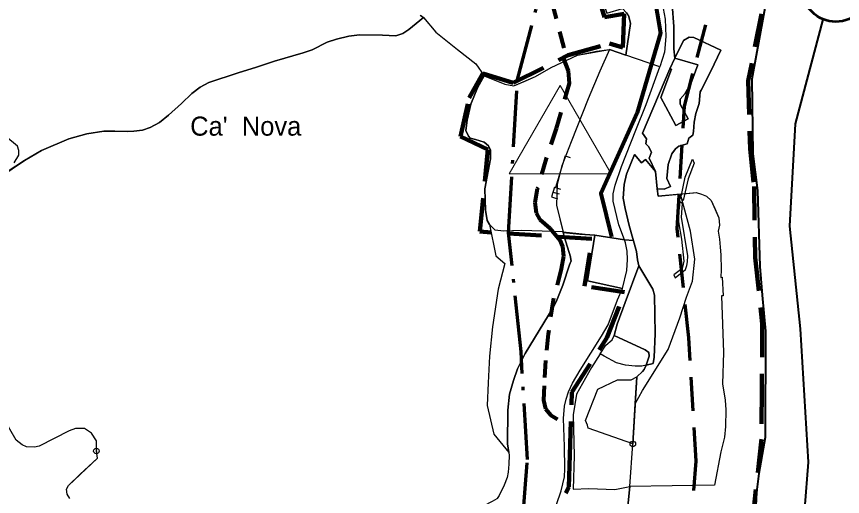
# Model space of a CAD drawing. Extents: x 645880 to 658994, y 884400 to 894744.
# Drawn here: x 657672 to 658409, y 893255 to 893684 of the extents above; entities that cross this region are included whole.
import ezdxf
from ezdxf.enums import TextEntityAlignment as Align

# ---------------------------------------------------------------- set-up
doc = ezdxf.new("R2010")
doc.units = 0
doc.header["$LTSCALE"] = 10
doc.header["$PDMODE"] = 32
doc.header["$PDSIZE"] = 5
for name, pattern in [('DOT_DASHED', [7.7, 5, -1.2, 0.3, -1.2]), ('MEDIUM_DASHED', [4.5, 3, -1.5]), ('SHORT_DASHED', [2.7, 1.5, -1.2])]:
    doc.linetypes.add(name, pattern=pattern)
for name, color, linetype, lineweight in [('1', 7, 'Continuous', 25), ('11', 7, 'Continuous', 25), ('13', 7, 'Continuous', 25), ('15', 7, 'MEDIUM_DASHED', 100), ('16', 7, 'Continuous', 25), ('17', 7, 'Continuous', 25), ('23', 7, 'Continuous', 25), ('29', 7, 'Continuous', 25), ('31', 7, 'Continuous', 25), ('40', 7, 'Continuous', 80), ('41', 7, 'Continuous', 40), ('43', 7, 'Continuous', 25), ('45', 7, 'Continuous', 25), ('55', 7, 'Continuous', 25), ('58', 7, 'Continuous', 25), ('59', 7, 'Continuous', 40), ('6', 7, 'Continuous', 25), ('8', 7, 'Continuous', 25)]:
    doc.layers.add(name, color=color, linetype=linetype, lineweight=lineweight)
doc.layers.add('60', color=7, linetype='Continuous')

msp = doc.modelspace()

# ---------------------------------------------------------------- linework, layer by layer
at = {"layer": '1'}
msp.add_lwpolyline([(658254.57, 893636.97), (658256.11, 893636.78), (658246.68, 893611.35), (658259.96, 893586.31), (658270.93, 893592.48), (658263.81, 893605.38), (658263.81, 893610), (658268.43, 893614.82), (658273.24, 893623.49), (658279.59, 893640.44), (658259, 893646.54)], close=True, dxfattribs=at)
for points in [[(658221.65, 893302.26), (658181.77, 893316.46), (658181.34, 893319.06), (658179.34, 893323.06), (658190.47, 893351.06), (658208.09, 893359.56)], [(658208.09, 893359.56), (658220.22, 893359.56), (658225.09, 893362.17), (658221.65, 893302.26)]]:
    msp.add_lwpolyline(points, dxfattribs=at)
msp.add_point((658221.65, 893302.26), dxfattribs=at)
at = {"layer": '11'}
msp.add_lwpolyline([(658203.33, 893395.05), (658205.08, 893398.92), (658232.75, 893386.21), (658235.81, 893383.96), (658236.17, 893380.56), (658234.55, 893375.56), (658233.57, 893372.65), (658229.56, 893371.79), (658223.86, 893371.79), (658214.98, 893372.47), (658207.14, 893374.72), (658196.05, 893380.49), (658192.6, 893382.61), (658197.59, 893390.43)], close=True, dxfattribs=at)
at = {"layer": '13'}
for points in [[(658192.6, 893382.61), (658184.84, 893370.51), (658171.43, 893346.66), (658168.44, 893328.22), (658169.34, 893291.72), (658168.29, 893261.9), (658182.5, 893262.45), (658205.56, 893261.71), (658218.93, 893264.19), (658221.65, 893302.26), (658181.77, 893316.46), (658181.34, 893319.06), (658179.34, 893323.06), (658190.47, 893351.06), (658208.09, 893359.56), (658220.22, 893359.56), (658225.09, 893362.17), (658230.3, 893366.95), (658231.67, 893368.82), (658232.92, 893371.32)], [(658232.92, 893371.32), (658233.57, 893372.65), (658229.56, 893371.79), (658223.86, 893371.79), (658214.98, 893372.47), (658207.14, 893374.72), (658196.05, 893380.49), (658192.6, 893382.61)]]:
    msp.add_lwpolyline(points, dxfattribs=at)
at = {"layer": '15'}
for points in [[(658271.86, 893859.9), (658294.4, 893888.67), (658333.87, 893869.22), (658397.09, 893835.57), (658355.34, 893760.97), (658345.21, 893730.15), (658324.56, 893626.35), (658326.18, 893565.54), (658329.82, 893531.88), (658330.62, 893468.63), (658337.11, 893409.83), (658336.7, 893350.23), (658336.29, 893306.44), (658326.56, 893216.03)], [(658141.8, 893218.08), (658164.49, 893263.9), (658165.31, 893292.28), (658167.33, 893348.61), (658198.53, 893396.86), (658214.34, 893437.82), (658178.68, 893443.09), (658185.17, 893485.26), (658085.26, 893491.71), (658092.37, 893565.14), (658068.06, 893576.49), (658075.76, 893610.95), (658087.91, 893632.85), (658115.06, 893624.33), (658164.09, 893649.07), (658200.96, 893659.61), (658212.72, 893655.96), (658213.93, 893685.96), (658196.51, 893683.12), (658187.58, 893713.13)]]:
    msp.add_lwpolyline(points, dxfattribs=at)
at = {"layer": '16'}
msp.add_lwpolyline([(657669.76, 893553.16), (657674.01, 893559.93), (657674.11, 893563.98), (657672.88, 893568.11), (657662.51, 893576.7)], dxfattribs=at)
at = {"layer": '17'}
for points in [[(658032.01, 893684.94), (658034.95, 893682.87), (658021.82, 893672.16), (658016.4, 893668.46), (658010.12, 893666.52), (657998.4, 893666.94), (657977.8, 893667.16), (657968.26, 893666.08), (657957.2, 893663.48), (657948.96, 893660.66), (657935.52, 893653.92), (657927.5, 893651.1), (657901.92, 893643.72), (657885.86, 893638.52), (657869.6, 893633.32), (657843.58, 893624.86), (657835.78, 893620.74), (657828.4, 893615.08), (657819.08, 893606.18), (657807.36, 893595.56), (657799.56, 893589.04), (657791.1, 893584.7), (657784.16, 893582.32), (657776.58, 893581.24), (657770.72, 893581.02), (657759.66, 893581.46), (657749.9, 893581.46), (657734.72, 893579.06), (657718.72, 893574.38), (657694.26, 893564.16), (657678.94, 893555.26), (657664.52, 893545.6)], [(657807.36, 893595.56), (657819.08, 893606.18), (657828.4, 893615.08), (657835.78, 893620.74), (657843.58, 893624.86), (657869.6, 893633.32), (657885.86, 893638.52), (657901.92, 893643.72), (657927.5, 893651.1), (657935.52, 893653.92), (657948.96, 893660.66), (657957.2, 893663.48), (657968.26, 893666.08), (657977.8, 893667.16), (657998.4, 893666.94), (658010.12, 893666.52), (658016.4, 893668.46), (658021.82, 893672.16), (658021.82, 893672.16), (658034.95, 893682.87), (658045.9, 893669.76), (658065.2, 893654.14), (658081.68, 893641.56), (658089.12, 893630.86), (658082.98, 893620.06), (658077.06, 893605.48), (658073.9, 893591.18), (658072.62, 893582.08), (658074.94, 893576.8), (658076.42, 893575.1), (658078.86, 893574.58), (658081.3, 893574.04), (658085.1, 893572.78), (658088.9, 893571.5), (658092.92, 893568.34), (658094.82, 893564.52), (658094.6, 893556.7), (658089.74, 893529.92), (658090.38, 893510.88), (658091.64, 893501.78), (658093.76, 893498.18)], [(657656.7, 893540.36), (657678.94, 893555.26), (657694.26, 893564.16), (657718.72, 893574.38), (657734.72, 893579.06), (657749.9, 893581.46), (657759.66, 893581.46), (657770.72, 893581.02), (657776.58, 893581.24), (657784.16, 893582.32), (657791.1, 893584.7), (657799.56, 893589.04), (657807.36, 893595.56)], [(657669.76, 893553.16), (657674.01, 893559.93), (657674.11, 893563.98), (657672.88, 893568.11), (657662.51, 893576.7)], [(658093.76, 893498.18), (658099.47, 893470.09), (658107.46, 893463.38), (658101.42, 893440.46), (658096.54, 893406.63), (658093.83, 893380.57)], [(658187.72, 893488.65), (658174.36, 893489.35), (658159.58, 893490.91)], [(658159.58, 893490.91), (658160.45, 893487.38), (658166.18, 893469.21)], [(658212.49, 893441.12), (658181.08, 893447.74), (658187.72, 893488.64)], [(658166.18, 893469.21), (658166.47, 893466.66), (658166.56, 893465.61), (658165.26, 893462.03), (658159.28, 893443.84), (658153.39, 893429.02)], [(658085.38, 893195.06), (658094.98, 893197.2), (658106.44, 893201.12), (658121.82, 893208.1), (658134.52, 893216.7), (658142.56, 893225.66), (658145.96, 893231.74), (658153.66, 893248.38), (658157.6, 893260.38), (658160.82, 893273.08), (658161, 893280.06), (658160.64, 893299.92), (658159.92, 893324.98), (658160.64, 893335.9), (658162.24, 893342.34), (658164.22, 893348.78), (658167.8, 893356.48), (658174.76, 893368.12), (658193.74, 893398.56), (658199.64, 893408.58), (658207.86, 893430.96), (658212.5, 893441.11)], [(658153.39, 893429.02), (658150.62, 893424.01), (658138.04, 893403.48)], [(658138.04, 893403.48), (658125.48, 893382.95), (658118.84, 893369.31), (658115.14, 893358.95)], [(658093.83, 893380.57), (658092.56, 893356.78), (658091.6, 893336.67), (658097.69, 893311.05), (658110.91, 893294.77)], [(658115.14, 893358.95), (658111.52, 893346.72), (658110.18, 893332.4)], [(657732.7, 893315.98), (657729.16, 893316.2), (657724.48, 893316.2), (657718.92, 893313.98), (657692.26, 893300.2), (657688.04, 893299.52), (657680.92, 893299.74), (657676.92, 893301.52), (657671.6, 893305.52), (657655.6, 893333.1)], [(658110.18, 893332.4), (658109.88, 893302.5), (658110.91, 893294.77)], [(657719.58, 893253.72), (657717.14, 893257.5), (657716.48, 893261.94), (657718.26, 893265.06), (657728.48, 893275.06), (657744.04, 893289.52), (657743.16, 893295.98), (657743.38, 893305.08), (657738.94, 893311.76), (657732.7, 893315.98), (657729.16, 893316.2), (657724.48, 893316.2), (657718.92, 893313.98), (657692.26, 893300.2), (657688.04, 893299.52), (657680.92, 893299.74), (657676.92, 893301.52), (657671.6, 893305.52)], [(657719.58, 893253.72), (657717.14, 893257.5), (657716.48, 893261.94), (657718.26, 893265.06), (657744.04, 893289.52), (657743.16, 893295.98), (657743.38, 893305.08), (657738.94, 893311.76), (657732.7, 893315.98)], [(658110.91, 893294.77), (658111.25, 893292.29), (658111.1, 893284.1), (658110.58, 893277.1), (658109.49, 893272.37), (658106.8, 893265.52), (658102.48, 893256.3), (658100.61, 893253.67), (658100.3, 893253.42), (658096.11, 893250.82), (658088.67, 893247.03), (658082.93, 893245.51), (658068.56, 893241.98), (658059.08, 893238.95)], [(658110.91, 893294.77), (658111.25, 893292.29), (658111.1, 893284.1), (658110.58, 893277.1), (658109.49, 893272.37), (658106.8, 893265.52), (658102.48, 893256.3), (658100.61, 893253.67), (658100.3, 893253.42), (658096.11, 893250.82), (658088.67, 893247.03), (658082.93, 893245.51), (658068.56, 893241.98), (658059.08, 893238.95), (658062.89, 893238.62), (658071.37, 893236.58)]]:
    msp.add_lwpolyline(points, dxfattribs=at)
msp.add_point((657743.16, 893295.98), dxfattribs=at)
at = {"layer": '23'}
msp.add_lwpolyline([(658239.84, 893374.06), (658240.73, 893379.64), (658241.57, 893400.63), (658241.01, 893434.89), (658241.01, 893434.89), (658239.34, 893440.45), (658239.34, 893440.45), (658226.86, 893461.24), (658225.87, 893466.59), (658224.9, 893473.91), (658218.37, 893497.27), (658214.77, 893512.21), (658212.96, 893521.52), (658213.93, 893533.89), (658216.02, 893542.87), (658223.24, 893560.66), (658229.5, 893553.15), (658232.97, 893555.93), (658242, 893545.51), (658243.49, 893529.98), (658244.34, 893523.48), (658275.65, 893526.23), (658278.09, 893526.48), (658282.92, 893525.16), (658287.22, 893523.48), (658291.47, 893519.48), (658294.72, 893512.48), (658298.34, 893503.98), (658298.97, 893497.48), (658297.84, 893491.98), (658298.84, 893484.98), (658299.53, 893477.98), (658300.22, 893470.98), (658300.34, 893457.98), (658300.09, 893450.92), (658301.34, 893450.98), (658302.22, 893434.48), (658300.83, 893434.36), (658301.71, 893409.17), (658302.59, 893383.98), (658301.59, 893355.98), (658304.02, 893341.45), (658304.57, 893332.63), (658304.43, 893317.75), (658303.32, 893308.44), (658302.36, 893303.57), (658300.11, 893295.25), (658294.5, 893265.58), (658218.93, 893264.19), (658221.65, 893302.26), (658225.09, 893362.17), (658230.3, 893366.95), (658231.67, 893368.82), (658233.57, 893372.65)], close=True, dxfattribs=at)
for points in [[(658233.57, 893372.65), (658239.84, 893374.06), (658240.73, 893379.64), (658241.57, 893400.63), (658241.01, 893434.89), (658239.34, 893440.45), (658226.86, 893461.24), (658214.69, 893428.53), (658207.82, 893409.29)], [(658207.82, 893409.29), (658205.08, 893398.92), (658232.75, 893386.21), (658235.81, 893383.96), (658236.17, 893380.56), (658233.57, 893372.65)]]:
    msp.add_lwpolyline(points, dxfattribs=at)
at = {"layer": '29'}
for points in [[(658159.41, 893491.6), (658159.08, 893491.64), (658122.25, 893492.7), (658106.23, 893492.27), (658098.83, 893493.12), (658093.76, 893498.19), (658091.64, 893501.79), (658090.38, 893510.88), (658089.74, 893529.92), (658094.6, 893556.71), (658094.81, 893564.53), (658092.91, 893568.34), (658088.9, 893571.51), (658081.29, 893574.05), (658076.42, 893575.11), (658074.94, 893576.8), (658072.62, 893582.08), (658073.89, 893591.18), (658077.06, 893605.48), (658082.98, 893620.07), (658089.11, 893630.86), (658107.5, 893623.24), (658115.53, 893621.76), (658124.62, 893625.57), (658134.76, 893630.01), (658148.93, 893638.26), (658162.88, 893644.6), (658172.39, 893649.26), (658189.3, 893652.64), (658200.71, 893654.12)], [(658200.71, 893654.12), (658192.12, 893634.81), (658181.89, 893610.19), (658166.71, 893571.87), (658158.35, 893550.54), (658154.22, 893534.01)], [(658200.71, 893654.12), (658192.12, 893634.81), (658181.89, 893610.19), (658166.71, 893571.87), (658158.35, 893550.54), (658154.22, 893534.01)], [(658214.15, 893484.45), (658209.15, 893497.74), (658204.07, 893518.89), (658204.07, 893525.44), (658205.98, 893533.27), (658211.46, 893549.92), (658224.35, 893582.22), (658233.44, 893605.27), (658245.7, 893638.69), (658215.38, 893649.09), (658200.71, 893654.12)], [(658154.22, 893534.01), (658153.55, 893515.32), (658159.41, 893491.6), (658187.72, 893488.65), (658214.15, 893484.45)], [(658154.22, 893534.01), (658153.55, 893515.32), (658159.41, 893491.6)]]:
    msp.add_lwpolyline(points, dxfattribs=at)
at = {"layer": '31'}
for points in [[(658032.89, 893684.43), (658034.95, 893682.87), (658045.9, 893669.76), (658065.2, 893654.14), (658081.68, 893641.56)], [(658081.68, 893641.56), (658089.11, 893630.86), (658107.5, 893623.24), (658115.53, 893621.76), (658134.76, 893630.01), (658148.93, 893638.26), (658172.39, 893649.26), (658200.71, 893654.12), (658215.38, 893649.09), (658219.44, 893677.54), (658217.97, 893683.8)]]:
    msp.add_lwpolyline(points, dxfattribs=at)
at = {"layer": '40'}
msp.add_lwpolyline([(658295.38, 893902.63), (658239.03, 893844.15), (658220.24, 893804.47), (658234.85, 893737.64), (658246.33, 893668.72), (658225.46, 893597.71), (658193.11, 893525.66), (658202.5, 893487.02)], dxfattribs=at)
at = {"layer": '40', "lineweight": 13}
msp.add_lwpolyline([(658156.91, 893621.98), (658202.39, 893543.22), (658111.45, 893543.22)], close=True, dxfattribs=at)
at = {"layer": '41', "linetype": 'SHORT_DASHED', "lineweight": 80}
for points in [[(658135.58, 893749.15), (658142.74, 893722.59), (658163.03, 893644.67)], [(658159.84, 893645.97), (658164.05, 893635.3), (658164.78, 893624.03), (658153.15, 893583.65), (658144.42, 893557.09), (658136.42, 893529.8), (658134.24, 893517.8), (658135.33, 893508.34), (658138.6, 893502.52), (658147.69, 893494.88), (658156.42, 893483.97), (658158.97, 893478.51), (658159.69, 893469.77), (658157.87, 893458.5), (658150.5, 893430.49), (658146.17, 893400.48), (658143.7, 893376.65), (658142.49, 893354.25), (658141.88, 893341.36), (658143.7, 893333.72), (658148.42, 893327.9), (658154.6, 893324.26)]]:
    msp.add_lwpolyline(points, dxfattribs=at)
at = {"layer": '41', "lineweight": 25}
for points in [[(658106.23, 893492.27), (658098.84, 893493.12), (658093.76, 893498.18)], [(658093.76, 893498.18), (658099.47, 893470.09), (658107.46, 893463.38), (658101.42, 893440.46), (658096.54, 893406.63), (658093.83, 893380.57)], [(658159.41, 893491.6), (658159.08, 893491.64), (658122.26, 893492.7), (658106.24, 893492.26)], [(658110.91, 893294.77), (658109.88, 893302.5), (658110.18, 893332.4), (658111.52, 893346.72), (658115.14, 893358.95), (658118.84, 893369.31), (658125.48, 893382.95), (658138.04, 893403.48), (658150.62, 893424.01), (658153.39, 893429.02), (658159.28, 893443.84), (658165.26, 893462.03), (658166.56, 893465.61), (658166.47, 893466.66), (658166.18, 893469.21), (658160.45, 893487.38), (658159.58, 893490.91), (658159.41, 893491.6)], [(658093.83, 893380.57), (658092.56, 893356.78), (658091.6, 893336.67), (658097.69, 893311.05), (658110.91, 893294.77)]]:
    msp.add_lwpolyline(points, dxfattribs=at)
at = {"layer": '43'}
for points in [[(658331.19, 893240.81), (658332.04, 893259.38), (658334.17, 893275.89), (658339.7, 893308.07), (658339.7, 893308.07), (658339.95, 893402.88), (658337.12, 893435.1), (658335, 893460.46), (658332.88, 893528.33), (658328.64, 893561.23), (658327.93, 893627.72), (658344.82, 893720.42), (658354, 893748.52), (658365.31, 893773.2), (658399.94, 893835.58), (658339.26, 893842.99), (658337.08, 893841.74), (658335.74, 893840.98)], [(658256.72, 893694.42), (658258.32, 893674.7), (658258.32, 893654.72), (658259, 893646.54), (658266.93, 893662.14), (658272.03, 893665.22), (658275.95, 893665), (658300.19, 893653.48), (658291.22, 893634.81), (658282.46, 893617.87), (658281.84, 893616.48), (658280.84, 893605.98), (658277.97, 893596.98), (658276.34, 893589.48), (658276.06, 893585.23), (658275.78, 893580.98), (658275.28, 893577.73), (658271.59, 893574.98), (658270.22, 893569.98), (658262.59, 893567.98), (658259.72, 893565.48), (658256.47, 893560.98), (658253.22, 893551.48), (658251.97, 893538.98), (658255.22, 893531.98), (658249.47, 893529.48), (658243.49, 893529.98), (658244.34, 893523.48), (658278.09, 893526.48), (658282.92, 893525.16), (658287.22, 893523.48), (658291.47, 893519.48), (658298.34, 893503.98), (658298.97, 893497.48), (658297.84, 893491.98), (658298.84, 893484.98), (658299.53, 893477.98), (658300.22, 893470.98), (658300.34, 893457.98), (658300.09, 893450.92), (658301.34, 893450.98), (658302.22, 893434.48), (658300.83, 893434.36), (658301.71, 893409.17), (658302.59, 893383.98), (658301.59, 893355.98), (658304.02, 893341.45), (658304.57, 893332.63), (658304.43, 893317.75), (658303.32, 893308.44), (658302.36, 893303.57), (658300.11, 893295.25), (658294.5, 893265.58), (658218.93, 893264.19)], [(658218.93, 893264.19), (658216.91, 893243.9), (658210.89, 893226.77), (658204.63, 893211.65), (658198.43, 893201.5)]]:
    msp.add_lwpolyline(points, dxfattribs=at)
at = {"layer": '45', "linetype": 'DOT_DASHED', "lineweight": 70}
msp.add_lwpolyline([(658032.74, 891178.84), (657962.16, 891450), (657912.65, 891632.07), (657880.45, 891775.54), (657862.08, 891924.55), (657862.75, 892057.96), (657880.13, 892212.9), (657948.63, 892498.48), (658035.94, 892864.43), (658113.04, 893179.94), (658123.49, 893235.71), (658127.65, 893288.31), (658121.92, 893384.59), (658110.78, 893490.65), (658118.71, 893627.43), (658149.69, 893744.87)], dxfattribs=at)
at = {"layer": '45', "linetype": 'MEDIUM_DASHED', "lineweight": 70}
msp.add_lwpolyline([(658177.94, 891216.48), (658107.15, 891488.48), (658058.27, 891668.19), (658028.42, 891801.21), (658012.13, 891933.39), (658012.71, 892049.2), (658028.16, 892186.95), (658094.51, 892463.58), (658181.75, 892829.22), (658259.72, 893148.31), (658272.39, 893215.94), (658278, 893286.86), (658271.45, 893396.89), (658261.24, 893494.17), (658267.59, 893603.71), (658294.73, 893706.6)], dxfattribs=at)
at = {"layer": '45', "lineweight": 40}
msp.add_lwpolyline([(658258.34, 891300.89), (658203.84, 891513.99), (658155.35, 891692.27), (658127.07, 891818.31), (658112.16, 891939.28), (658112.68, 892043.36), (658126.85, 892169.65), (658191.77, 892440.31), (658278.96, 892805.75), (658357.51, 893127.22), (658371.66, 893202.76), (658378.23, 893285.88), (658371.14, 893405.08), (658361.54, 893496.51), (658366.84, 893587.91), (658391.42, 893681.1)], dxfattribs=at)
at = {"layer": '45', "lineweight": 53}
msp.add_circle((658402.69, 893708.9), 30, dxfattribs=at)
at = {"layer": '55'}
msp.add_line((658254.57, 893636.97), (658259, 893646.54), dxfattribs=at)
for points in [[(658187.45, 893801.94), (658195.59, 893788.81), (658197.94, 893783.01), (658196.42, 893778.31), (658191.48, 893773.41), (658194.76, 893767.92), (658174.95, 893757.6), (658188.51, 893717.27), (658198.45, 893686.6), (658212.47, 893690.69), (658216.01, 893687.03), (658217.97, 893683.8), (658219.44, 893677.54), (658215.38, 893649.09), (658200.71, 893654.12), (658192.12, 893634.81), (658181.89, 893610.19), (658166.71, 893571.87), (658158.35, 893550.54), (658154.22, 893534.01)], [(658259, 893646.54), (658258.32, 893654.72), (658258.32, 893674.7), (658256.72, 893694.42), (658253.96, 893715.11), (658253.33, 893724.66), (658254.81, 893744.86), (658251.05, 893748.63), (658248.12, 893752.81)], [(658242, 893545.51), (658236.35, 893557.37), (658238.22, 893562.75), (658235.68, 893567.72), (658233.26, 893570.13), (658233.8, 893574.55), (658230.32, 893579.65), (658254.57, 893636.97)], [(658264.23, 893525.23), (658244.34, 893523.48), (658243.49, 893529.98), (658242, 893545.51), (658232.97, 893555.93), (658229.5, 893553.15), (658223.24, 893560.66), (658216.02, 893542.87), (658213.93, 893533.89), (658212.96, 893521.52), (658214.77, 893512.21), (658218.37, 893497.27), (658224.9, 893473.91), (658225.87, 893466.59), (658226.86, 893461.24), (658239.34, 893440.45)], [(658213.93, 893533.89), (658216.02, 893542.87), (658223.24, 893560.66)], [(658223.24, 893560.66), (658229.5, 893553.15), (658232.97, 893555.93), (658242, 893545.51)], [(658154.22, 893534.01), (658153.55, 893515.32), (658159.58, 893490.91)], [(658222.12, 893483.86), (658218.37, 893497.27), (658214.77, 893512.21), (658212.96, 893521.52), (658213.93, 893533.89)], [(658223.7, 893337.94), (658230.35, 893349.84), (658253.22, 893386.45), (658263.64, 893414.83), (658269.58, 893433.12), (658274.95, 893447.41), (658276.93, 893467.28), (658272.98, 893492.08), (658264.23, 893525.23)], [(658159.58, 893490.91), (658160.45, 893487.38), (658166.18, 893469.21), (658166.47, 893466.66), (658166.56, 893465.61), (658165.26, 893462.03), (658159.28, 893443.84), (658153.39, 893429.02), (658150.62, 893424.01), (658138.04, 893403.48), (658125.48, 893382.95), (658118.84, 893369.31), (658115.14, 893358.95), (658111.52, 893346.72), (658110.18, 893332.4), (658109.88, 893302.5), (658111.25, 893292.29), (658111.1, 893284.1), (658110.58, 893277.1), (658109.49, 893272.37), (658106.8, 893265.52), (658102.48, 893256.3), (658100.61, 893253.67)], [(658159.58, 893490.91), (658174.36, 893489.35), (658187.72, 893488.65), (658214.16, 893484.45), (658222.12, 893483.86)], [(658187.72, 893488.65), (658174.36, 893489.35), (658159.58, 893490.91)], [(658226.86, 893461.24), (658225.87, 893466.59), (658224.9, 893473.91), (658222.12, 893483.86), (658214.16, 893484.45), (658187.72, 893488.65)], [(658239.84, 893374.06), (658240.73, 893379.64), (658241.57, 893400.63), (658241.01, 893434.89), (658239.34, 893440.45), (658226.86, 893461.24), (658214.69, 893428.53), (658207.82, 893409.29), (658205.08, 893398.92)], [(658207.82, 893409.29), (658214.69, 893428.53), (658226.86, 893461.24)], [(658239.34, 893440.45), (658241.01, 893434.89), (658241.57, 893400.63), (658240.73, 893379.64), (658239.84, 893374.06)], [(658233.57, 893372.65), (658236.17, 893380.56), (658235.81, 893383.96), (658232.75, 893386.21), (658205.08, 893398.92), (658207.82, 893409.29)], [(658205.08, 893398.92), (658232.75, 893386.21), (658235.81, 893383.96), (658236.17, 893380.56), (658233.57, 893372.65), (658239.84, 893374.06)], [(658239.84, 893374.06), (658233.57, 893372.65), (658231.67, 893368.82), (658230.3, 893366.95), (658225.09, 893362.17), (658223.7, 893337.94)], [(658223.7, 893337.94), (658225.09, 893362.17), (658230.3, 893366.95), (658231.67, 893368.82), (658233.57, 893372.65)], [(658218.93, 893264.19), (658221.65, 893302.26), (658223.7, 893337.94)], [(658198.43, 893201.5), (658204.63, 893211.65), (658210.89, 893226.77), (658216.91, 893243.9), (658218.93, 893264.19)]]:
    msp.add_lwpolyline(points, dxfattribs=at)
at = {"layer": '58'}
for points in [[(658264.37, 893521.55), (658268.18, 893540.25), (658274.74, 893556.31), (658276.49, 893552.87)], [(658276.49, 893552.87), (658270.93, 893538.94), (658266.63, 893519.47), (658264.37, 893521.55)], [(658263.55, 893518.44), (658262.49, 893507.69), (658262.49, 893500.56), (658265.18, 893485.13), (658267.12, 893465.5), (658266.05, 893459.87), (658264.12, 893457.5), (658258.31, 893453.25), (658259.51, 893450.5)], [(658259.51, 893450.5), (658268.62, 893458.06), (658269.93, 893461.5), (658270.43, 893464.81), (658270.62, 893470.25), (658265.12, 893504.5), (658266.05, 893516.69), (658263.55, 893518.44)]]:
    msp.add_lwpolyline(points, dxfattribs=at)
at = {"layer": '59'}
for points in [[(658344.82, 893720.42), (658327.93, 893627.72), (658328.64, 893561.23), (658332.88, 893528.33), (658335, 893460.46), (658337.12, 893435.1)], [(658337.12, 893435.1), (658339.95, 893402.88), (658339.7, 893308.07), (658334.17, 893275.89), (658332.04, 893259.38), (658331.19, 893240.81)]]:
    msp.add_lwpolyline(points, dxfattribs=at)
at = {"layer": '6'}
for p, q in [((658161.21, 893559.27), (658152.69, 893531.02)), ((658161.21, 893559.27), (658165.62, 893557.94)), ((658151.73, 893531.31), (658149.14, 893522.7)), ((658151.73, 893531.31), (658157.11, 893529.69)), ((658149.14, 893522.7), (658154.51, 893521.08)), ((658150.43, 893527.01), (658155.81, 893525.39))]:
    msp.add_line(p, q, dxfattribs=at)
at = {"layer": '8'}
msp.add_line((658242, 893545.51), (658243.49, 893529.98), dxfattribs=at)
for points in [[(658248.74, 893690.89), (658250.43, 893681.22), (658251.07, 893665.94), (658249.8, 893651.92), (658245.7, 893638.69), (658215.38, 893649.09), (658219.44, 893677.54), (658217.97, 893683.8)], [(658243.49, 893529.98), (658249.47, 893529.48), (658255.22, 893531.98), (658251.97, 893538.98), (658253.22, 893551.48), (658256.47, 893560.98), (658259.72, 893565.48), (658262.59, 893567.98), (658270.22, 893569.98), (658271.59, 893574.98), (658275.28, 893577.73), (658275.78, 893580.98), (658276.06, 893585.23), (658276.34, 893589.48), (658277.97, 893596.98), (658280.84, 893605.98), (658281.84, 893616.48), (658282.46, 893617.87), (658291.22, 893634.81), (658300.19, 893653.48), (658275.95, 893665), (658272.03, 893665.22), (658266.93, 893662.14), (658259, 893646.54)], [(658259, 893646.54), (658279.59, 893640.44), (658273.24, 893623.49), (658268.43, 893614.82), (658263.81, 893610), (658263.81, 893605.38), (658270.93, 893592.48), (658259.96, 893586.31), (658246.68, 893611.35), (658256.11, 893636.78), (658254.57, 893636.97), (658230.32, 893579.65)], [(658230.32, 893579.65), (658233.8, 893574.55), (658233.26, 893570.13), (658235.68, 893567.72), (658238.22, 893562.75), (658236.35, 893557.37), (658242, 893545.51)], [(658187.72, 893488.65), (658181.07, 893447.74), (658212.49, 893441.12)], [(658216.81, 893466.91), (658216.54, 893474.34), (658215.04, 893481.84), (658214.16, 893484.45), (658187.72, 893488.65)], [(658212.49, 893441.12), (658216.22, 893457.01), (658216.81, 893466.91)]]:
    msp.add_lwpolyline(points, dxfattribs=at)

# ---------------------------------------------------------------- texts
at = {"layer": '60'}
msp.add_text("Ca'  Nova", height=17, dxfattribs=at).set_placement((657876.38, 893577.34), align=Align.CENTER)

doc.saveas('drawing.dxf')
